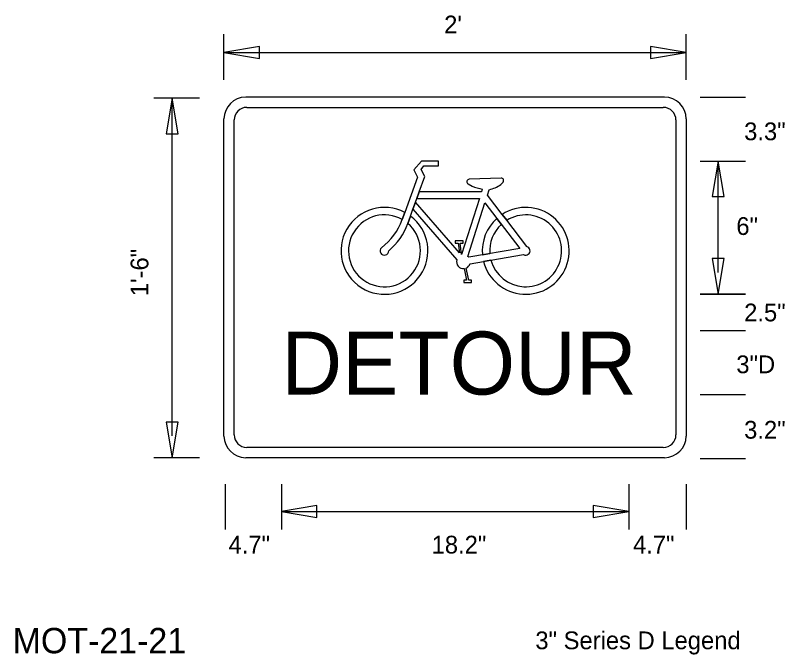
# Model space of a CAD drawing. Extents: x 0 to 770, y 0 to 495.
# Drawn here: x 587.2 to 738.6, y 348.1 to 474.1 of the extents above; entities that cross this region are included whole.
import ezdxf

# ---------------------------------------------------------------- set-up
doc = ezdxf.new("R2010")
doc.units = 0
for name, color, linetype in [('Default', 7, 'Continuous'), ('Dimension', 7, 'Continuous'), ('GSDims', 7, 'Continuous'), ('TextStructures', 7, 'Continuous')]:
    doc.layers.add(name, color=color, linetype=linetype)

msp = doc.modelspace()

# ---------------------------------------------------------------- linework, layer by layer
at = {"layer": 'Default'}
for p, q in [((670.49, 445.39), (667.15, 445.39)), ((676.33, 440.89), (677.12, 440.46)), ((682.83, 442.03), (676.54, 441.79)), ((682.75, 440.76), (683.19, 441.22)), ((666.69, 439.34), (666.22, 438.02)), ((678.94, 439.34), (666.69, 439.34)), ((679.11, 439.86), (678.94, 439.34)), ((680.12, 438.7), (680.45, 439.75)), ((666.22, 438.02), (678.53, 438.02)), ((678.53, 438.02), (675.03, 426.97)), ((683.01, 434.89), (680.12, 438.7)), ((665.45, 435.88), (665.96, 437.3)), ((665.96, 437.3), (665.45, 435.88)), ((674.6, 427.3), (665.96, 437.3)), ((676.29, 426.6), (679.64, 437.17)), ((679.64, 437.17), (686.48, 428.16)), ((663.32, 433.87), (663.83, 435.28)), ((665.45, 435.88), (674.07, 425.9)), ((683.91, 433.71), (683.01, 434.89)), ((683.01, 434.89), (683.91, 433.71)), ((664.97, 434.56), (664.44, 433.09)), ((682.86, 432.92), (681.97, 434.1)), ((687.85, 428.53), (683.91, 433.71)), ((673.8, 429.66), (673.8, 429.2)), ((673.8, 429.2), (674.36, 429.2)), ((674.36, 429.2), (674.6, 427.3)), ((675.03, 426.97), (674.77, 429.2)), ((674.77, 429.2), (675.33, 429.2)), ((686.48, 428.16), (676.44, 426.46)), ((679.14, 426.92), (680.6, 427.16)), ((679.36, 425.62), (680.82, 425.87)), ((680.82, 425.87), (679.36, 425.62)), ((680.82, 425.87), (687.25, 426.96)), ((675.53, 424.19), (676.03, 421.91)), ((676.43, 421.91), (675.93, 424.29)), ((676.72, 425.17), (679.36, 425.62)), ((676.03, 421.91), (675.47, 421.91)), ((675.47, 421.91), (675.47, 421.45)), ((675.47, 421.45), (677, 421.45)), ((677, 421.91), (676.43, 421.91)), ((677, 421.45), (677, 421.91))]:
    msp.add_line(p, q, dxfattribs=at)
for points in [[(714.99, 457.98), (632.51, 457.98)], [(632.74, 455.97), (714.76, 455.97)], [(628.24, 391.21), (628.24, 453.72)], [(630.26, 391.45), (630.26, 453.48)], [(717.24, 453.48), (717.24, 391.45)], [(719.26, 453.72), (719.26, 391.21)], [(667.15, 445.39), (665.61, 443.64), (666.34, 442.24)], [(667.77, 442.35), (667.05, 443.75), (667.6, 444.45), (670.49, 444.46), (670.49, 445.39)], [(666.34, 442.24), (663.83, 435.28), (663.32, 433.87)], [(665.96, 437.3), (666.22, 438.02), (666.69, 439.34), (667.77, 442.35)], [(664.44, 433.09), (664.97, 434.56), (665.45, 435.88)], [(675.33, 429.2), (675.33, 429.66), (673.8, 429.66)], [(714.76, 388.97), (632.74, 388.97)], [(714.99, 386.95), (632.51, 386.95)]]:
    msp.add_lwpolyline(points, dxfattribs=at)
for centre, radius, start, end in [((632.51, 453.71), 4.27, 90, 180), ((714.99, 453.71), 4.27, 0, 90), ((632.74, 453.48), 2.49, 90, 180), ((714.76, 453.48), 2.49, 0, 90), ((676.55, 441.31), 0.479, 92.1879, 241.7383), ((682.84, 441.55), 0.479, 316.3782, 92.1879), ((680.34, 447.49), 7.73, 245.4282, 260.8725), ((679.08, 446.01), 6.41, 282.3799, 304.8848), ((659.84, 427.7), 8.56, 62.2242, 53.2082), ((659.84, 427.7), 7.08, 60.5514, 49.5247), ((687.66, 427.7), 8.56, 194.074, 122.8745), ((687.66, 427.7), 7.08, 195.0056, 121.9665), ((652, 437.89), 12.02, 307.0505, 340.4631), ((687.66, 427.7), 8.56, 131.6776, 185.2709), ((653.07, 437.02), 12.03, 309.3066, 340.9436), ((687.66, 427.7), 7.08, 132.6092, 184.3629), ((659.84, 427.7), 0.848, 135.204, 0.469), ((687.66, 427.7), 0.848, 241.3441, 77.2895), ((675.4, 425.56), 1.37, 165.5006, 275.5282), ((675.4, 425.56), 1.37, 40.9558, 49.6323), ((675.4, 425.56), 1.37, 292.8768, 343.7536), ((632.51, 391.22), 4.27, 180, 270), ((632.74, 391.45), 2.49, 180, 270), ((714.76, 391.45), 2.49, 270, 360), ((714.99, 391.22), 4.27, 270, 360)]:
    msp.add_arc(centre, radius, start, end, dxfattribs=at)
at = {"layer": 'Dimension'}
for points in [[(628.24, 466.79), (635.26, 465.6), (635.26, 467.97)], [(719.26, 466.79), (712.24, 467.97), (712.24, 465.6)], [(618.02, 457.78), (616.83, 450.76), (619.21, 450.76)], [(725.58, 445.39), (724.39, 438.38), (726.76, 438.38)], [(725.58, 419.14), (726.76, 426.16), (724.39, 426.16)], [(618.02, 386.95), (619.21, 393.97), (616.83, 393.97)], [(639.54, 376.35), (646.55, 375.16), (646.55, 377.54)], [(707.96, 376.35), (700.95, 377.54), (700.95, 375.16)]]:
    msp.add_lwpolyline(points, close=True, dxfattribs=at)
at = {"layer": 'GSDims'}
for p, q in [((628.24, 461.41), (628.24, 470.37)), ((719.26, 461.41), (719.26, 470.37)), ((628.24, 466.79), (719.26, 466.79)), ((623.4, 457.78), (614.44, 457.78)), ((618.02, 391.24), (618.02, 457.78)), ((721.99, 457.98), (730.95, 457.98)), ((721.99, 445.39), (730.95, 445.39)), ((725.58, 423.43), (725.58, 445.39)), ((721.99, 419.14), (730.95, 419.14)), ((730.95, 419.14), (721.99, 419.14)), ((721.99, 411.98), (730.95, 411.98)), ((721.99, 399.39), (730.95, 399.39)), ((623.4, 386.95), (614.44, 386.95)), ((721.99, 386.8), (730.95, 386.8)), ((628.44, 381.72), (628.44, 372.77)), ((639.54, 381.72), (639.54, 372.77)), ((707.96, 381.72), (707.96, 372.77)), ((719.26, 381.72), (719.26, 372.77)), ((639.54, 376.35), (707.96, 376.35))]:
    msp.add_line(p, q, dxfattribs=at)

# ---------------------------------------------------------------- texts
at = {"layer": 'Default'}
msp.add_text('DETOUR', height=12.394, dxfattribs=at).set_placement((639.54, 399.39))
at = {"layer": 'TextStructures'}
for s, height, p in [("2'", 3.5, (671.6, 470.54)), ('3.3"', 3.5, (730.68, 449.49)), ('6"', 3.5, (729.14, 430.83)), ('2.5"', 3.5, (730.68, 413.81)), ('3"D', 3.5, (729.14, 403.59)), ('3.2"', 3.5, (730.68, 390.7)), ('4.7"', 3.5, (629.14, 368.07)), ('18.2"', 3.5, (669.13, 368.07)), ('4.7"', 3.5, (708.79, 368.07)), ('MOT-21-21', 5, (586.61, 348.41)), ('3" Series D Legend', 3.5, (689.56, 349.21))]:
    msp.add_text(s, height=height, dxfattribs=at).set_placement(p)
msp.add_text('1\'-6"', height=3.5, rotation=90, dxfattribs=at).set_placement((613.35, 418.77))

doc.saveas('drawing.dxf')
